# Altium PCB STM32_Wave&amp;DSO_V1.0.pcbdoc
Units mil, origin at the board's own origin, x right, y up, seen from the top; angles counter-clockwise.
Board outline 3421.85 x 1989.65 mil, 2 copper layers (Top Layer, Bottom Layer); 68 components, 46 nets, 295 pads, 187 vias.
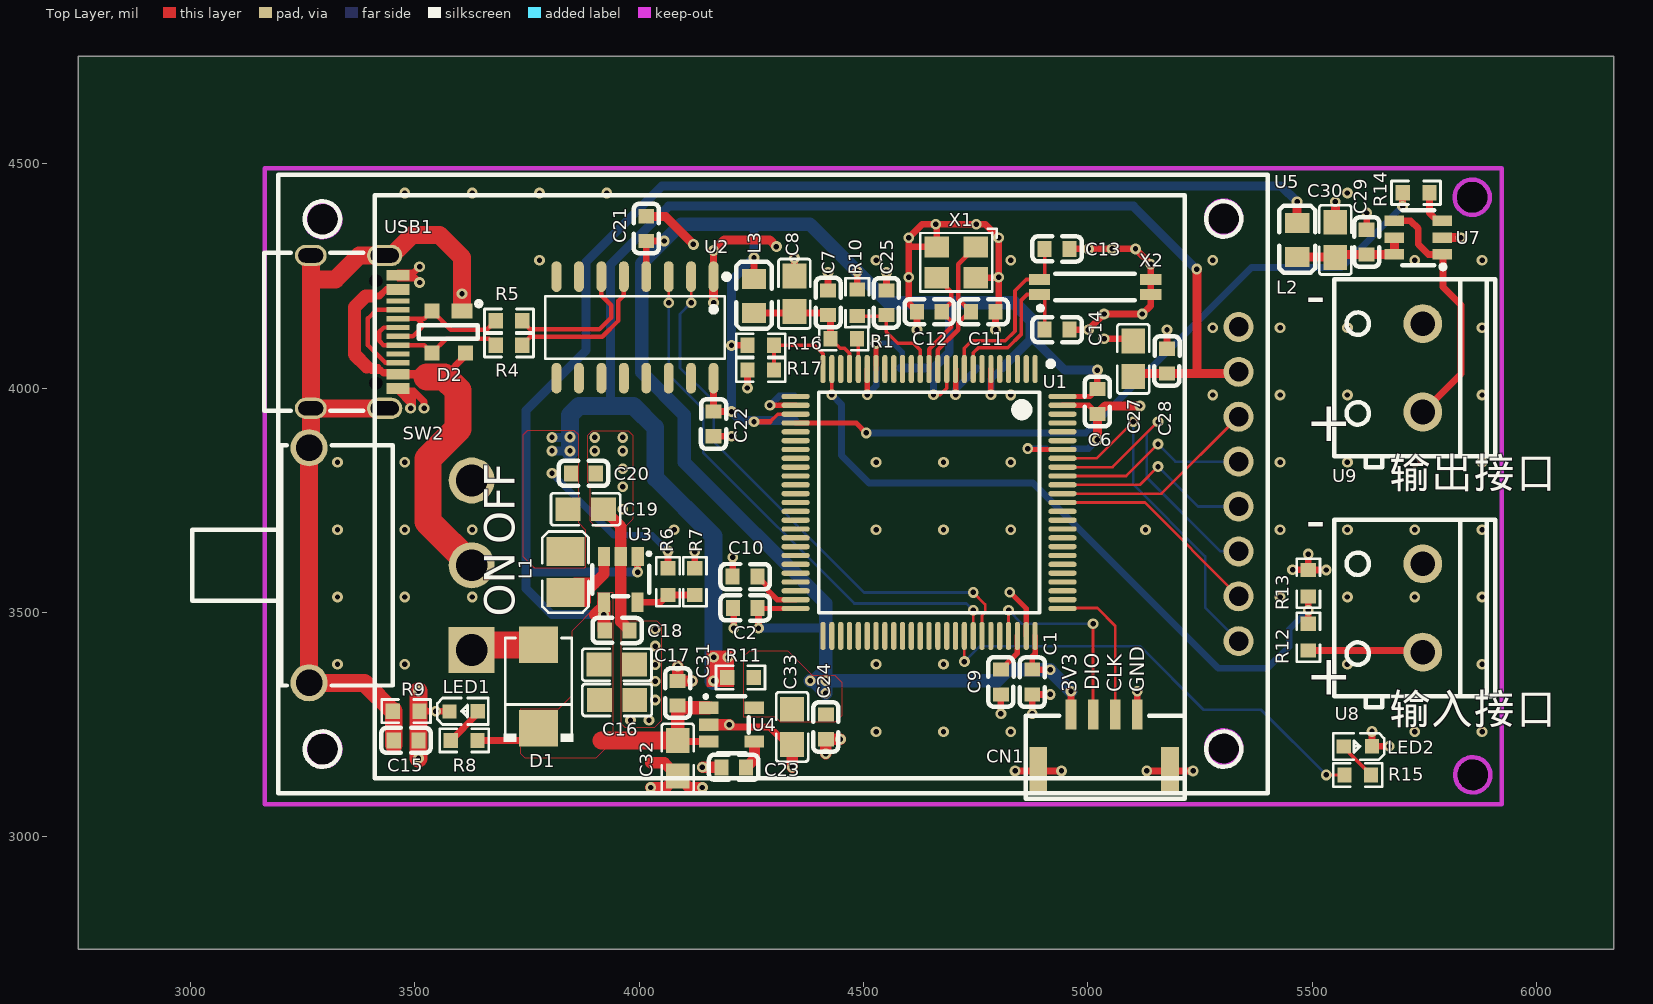
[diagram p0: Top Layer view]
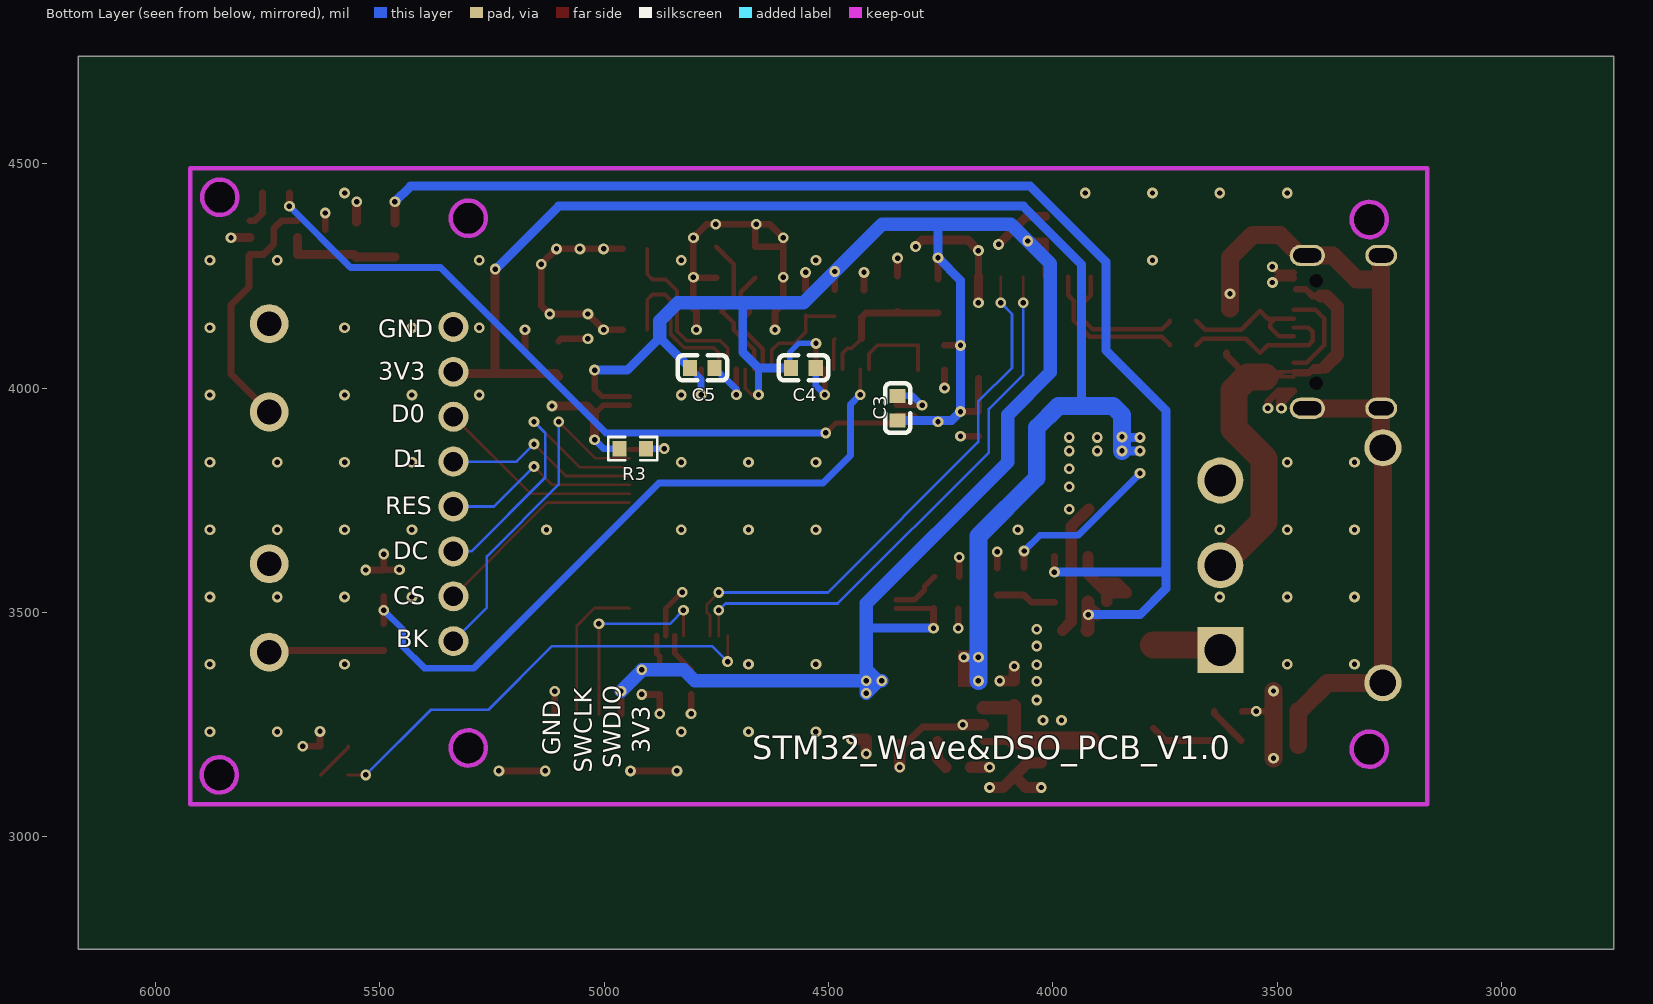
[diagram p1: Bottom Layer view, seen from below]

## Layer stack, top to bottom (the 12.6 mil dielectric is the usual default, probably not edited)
Top Layer: signal copper (thickness not stored)
Dielectric: dielectric 12.6, FR-4, Dk 4.8
Bottom Layer: signal copper (thickness not stored)

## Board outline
6171.85,2750 2750,2750 2750,4739.65 6171.85,4739.65
cut-out: 3334.43,4376.57 ccw(c3294.37,4376.57) 3254.31,4376.57 ccw(c3294.37,4376.57)
cut-out: 3334.41,3195.35 ccw(c3295.04,3195.35) 3255.67,3195.35 ccw(c3295.04,3195.35)
cut-out: 5341.57,3198.23 ccw(c5302.2,3198.23) 5262.83,3198.23 ccw(c5302.2,3198.23)
cut-out: 5896.57,3138.23 ccw(c5857.2,3138.23) 5817.83,3138.23 ccw(c5857.2,3138.23)
cut-out: 5895.31,4425 ccw(c5855.94,4425) 5816.57,4425 ccw(c5855.94,4425)
cut-out: 5342.25,4378.23 ccw(c5302.2,4378.23) 5262.16,4378.23 ccw(c5302.2,4378.23)

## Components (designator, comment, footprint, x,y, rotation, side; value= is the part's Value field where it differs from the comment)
C1 "0603B104K500NT" C0603 4875.94,3345 r90 top
C2 "0603B104K500NT" C0603 4236.55,3510 r0 top
C3 "0603B104K500NT" C0603 4345.94,3955 r270 bottom
C4 "0603B104K500NT" C0603 4555.94,4045 r0 bottom
C5 "0603B104K500NT" C0603 4781.06,4045 r0 bottom
C6 "0603B104K500NT" C0603 5020.94,3970 r90 top
C7 "0603B104K500NT" C0603 4420.94,4190 r270 top
C8 "GRM21BR61H106KE43L" C0805 4345.94,4210 r90 top
C9 "0603B104K500NT" C0603 4805.94,3345 r270 top
C10 "0603B104K500NT" C0603 4235.94,3580 r180 top
C11 "0603B104K500NT" C0603 4766.64,4170 r180 top
C12 "0603B104K500NT" C0603 4646.64,4170 r0 top
C13 "0603B104K500NT" C0603 4930.94,4310 r180 top
C14 "0603B104K500NT" C0603 4930.94,4130 r180 top
C15 "CAP_0603" C0603 3480.94,3215 r0 top
C16 "GRM21BR61H106KE43L" C0805 3950.94,3305 r180 top
C17 "GRM21BR61H106KE43L" C0805 3950.46,3383.67 r180 top
C18 "CC0603KRX7R9BB104" C0603 3950.94,3460 r180 top
C19 "GRM21BR61H106KE43L" C0805 3880.94,3730 r180 top
C20 "CC0603KRX7R9BB104" C0603 3875.94,3810 r180 top
C21 "CC0603KRX7R9BB104" C0603 4015.94,4355 r270 top
C22 "CC0603KRX7R9BB104" C0603 4165.94,3920 r90 top
C23 "CC0603KRX7R9BB104" C0603 4210.94,3155 r0 top
C24 "CC0603KRX7R9BB104" C0603 4415.94,3245 r90 top
C25 "0603B104K500NT" C0603 4550.94,4190 r90 top
C27 "GRM21BR61H106KE43L" C0805 5100.94,4065 r270 top
C28 "CC0603KRX7R9BB104" C0603 5175.94,4060 r270 top
C29 "CC0603KRX7R9BB104" C0603 5620.94,4325 r270 top
C30 "GRM21BR61H106KE43L" C0805 5550.94,4330 r270 top
C31 "CC0603KRX7R9BB104" C0603 4085.94,3320 r270 top
C32 "GRM21BR61H106KE43L" C0805 4085.94,3175 r90 top
C33 "GRM21BR61H106KE43L" C0805 4340.94,3245 r90 top
CN1 "X1251WRS-04HF-LPSW" CONN-SMD_4P-P1.25_X1251WRS-04HF-LPSW 5035.94,3210 r0 top
D1 "S2M_C232827" SMB_L4.6-W3.6-LS5.3-RD 3775.94,3335 r90 top
D2 "SESR05" SOT-143-4_L2.9-W1.3-P1.92-LS2.3-BL 3575.94,4125 r180 top
L1 "TFM252012ALMA4R7MTAA" L2520 3835.94,3590 r90 top
L2 "磁珠 0805 600Ω@100MHz CBW201209U601T" L0805 5465.94,4330 r270 top
L3 "磁珠 0805 600Ω@100MHz CBW201209U601T" L0805 4255.94,4205 r270 top
LED1 "LED_0603-R" LED_0603 3610.94,3280 r0 top
LED2 "LED_0603-R" LED_0603 5599.25,3201.55 r180 top
R1 "0603WAF0000T5E" R0603 4455.94,4110 r180 top
R3 "0603WAF0000T5E" R0603 4935.94,3865 r0 bottom
R4 "Res_0603" R0603 3710.26,4095 r180 top
R5 "Res_0603" R0603 3710.26,4150 r180 top
R6 "Res_0603" R0603 4064.2,3568.67 r270 top
R7 "Res_0603" R0603 4124.2,3568.67 r90 top
R8 "Res_0603" R0603 3610.26,3215 r0 top
R9 "Res_0603" R0603 3480.94,3280 r0 top
R10 "0603WAF0000T5E" R0603 4485.94,4190 r270 top
R11 "Res_0603" R0603 4225.94,3355 r180 top
R12 "Res_0603" R0603 5490.94,3445 r90 top
R13 "Res_0603" R0603 5490.94,3565 r90 top
R14 "Res_0603" R0603 5730.94,4435 r0 top
R15 "Res_0603" R0603 5601.13,3138.05 r180 top
R16 "0603WAF0000T5E" R0603 4270.94,4095 r0 top
R17 "0603WAF0000T5E" R0603 4270.94,4040 r180 top
SW2 "K3-1391B-51" SW-TH_K3-1391B-51 3445.94,3605 r270 top
U1 "STM32F407VET6" LQFP-100_L14.0-W14.0-P0.50-LS16.0-BL 4645.94,3745 r180 top
U2 "CH340C" SOP-16_L10.0-W3.9-P1.27-LS6.0-BL 3990.94,4135 r180 top
U3 "SY8089A1AAC" TSOT-23-5_L2.9-W1.6-P0.95-LS2.8-BR 3959.2,3573.67 r90 top
U4 "XC6228D122VR-G" TSOT-23-5_L2.9-W1.6-P0.95-LS2.8-BR 4205.94,3250 r180 top
U5 "TFT LCD 1.8" "TFT-LCD 1.8" 3185.94,4470 r270 top
U7 "OPA357AIDBVR" SOT-23-6_L2.9-W1.6-P0.95-LS2.8-BR 5735.94,4335 r0 top
U8 "KF300-5.0-2P" CONN-TH_P5.00_KF300-5.0-2P 5745.94,3510 r270 top
U9 "KF300-5.0-2P" CONN-TH_P5.00_KF300-5.0-2P 5745.94,4045 r270 top
USB1 "TYPE-C-31-M-12" USB-C_SMD-TYPE-C-31-M-12 3365.94,4125 r270 top
X1 "X32258MOB4SI" OSC-SMD_4P-L3.2-W2.5-BL 4706.64,4280 r180 top
X2 "M132768PWPAC" MC-146_4P-L6.7-W1.5-P0.85-BL 5015.94,4225 r0 top

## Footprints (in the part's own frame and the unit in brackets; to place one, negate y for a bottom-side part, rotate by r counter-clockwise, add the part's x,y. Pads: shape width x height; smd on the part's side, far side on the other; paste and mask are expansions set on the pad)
C0603 [mm]
  rect 0.8x0.9 smd paste+0 mask+0.051: 1(-0.7,0) 2(0.7,0)
  silkscreen extent -1.41,-0.71 1.39,0.72
C0805 [mm]
  rect 1.41x1.35 smd paste-100 mask+0.051: 1(-1,0) 2(1,0)
  silkscreen extent -1.96,-0.9 1.96,0.9
CONN-SMD_4P-P1.25_X1251WRS-04HF-LPSW [mm]
  rect 0.6x1.7 smd paste+0 mask+0.051: 1(-1.875,1.6) 2(-0.625,1.6) 3(0.625,1.6) 4(1.875,1.6)
  rect 1x2.7 smd paste+0 mask+0.051: 5(3.725,-1.6) 6(-3.725,-1.6)
  silkscreen extent -4.45,-3.18 4.57,1.52
CONN-TH_P5.00_KF300-5.0-2P [mm]
  round 2.2 hole 1.4 paste+0 mask+0.051: 1(2.5,0) 2(-2.5,0)
  silkscreen extent -5,-5 5.63,4.1
L0805 [mil]
  rect 44.59x54.21 smd paste-3937.01 mask+2: 1(-38.04,0) 2(38.04,0)
  silkscreen extent -77,-40 73,40
L2520 [mm]
  rect 1.635x2.16 smd paste-100 mask+0.051: 1(-1.168,0) 2(1.168,0)
  silkscreen extent -2.3,-1.31 2.3,1.31
LED_0603 [mil]
  rect 31.5x31.5 smd paste+0 mask+2: 1(-33.5,-0.4) 2(29.5,-0.2)
  silkscreen extent -61,-30 53,30
LQFP-100_L14.0-W14.0-P0.50-LS16.0-BL [mm]
  oval 0.3x1.6 smd paste-100 mask+0.051: 1(-6,-7.55) 2(-5.5,-7.55) 3(-5,-7.55) 4(-4.5,-7.55) 5(-4,-7.55) 6(-3.5,-7.55) 7(-3,-7.55) 8(-2.5,-7.55) 9(-2,-7.55) 10(-1.5,-7.55) 11(-1,-7.55) 12(-0.5,-7.55) 13(0,-7.55) 14(0.5,-7.55) 15(1,-7.55) 16(1.5,-7.55) 17(2,-7.55) 18(2.5,-7.55) 19(3,-7.55) 20(3.5,-7.55) 21(4,-7.55) 22(4.5,-7.55) 23(5,-7.55) 24(5.5,-7.55) 25(6,-7.55) 51(6,7.55) 52(5.5,7.55) 53(5,7.55) 54(4.5,7.55) 55(4,7.55) 56(3.5,7.55) 57(3,7.55) 58(2.5,7.55) 59(2,7.55) 60(1.5,7.55) 61(1,7.55) 62(0.5,7.55) 63(0,7.55) 64(-0.5,7.55) 65(-1,7.55) 66(-1.5,7.55) 67(-2,7.55) 68(-2.5,7.55) 69(-3,7.55) 70(-3.5,7.55) 71(-4,7.55) 72(-4.5,7.55) 73(-5,7.55) 74(-5.5,7.55) 75(-6,7.55)
  oval 1.6x0.3 smd paste-100 mask+0.051: 26(7.55,-6) 27(7.55,-5.5) 28(7.55,-5) 29(7.55,-4.5) 30(7.55,-4) 31(7.55,-3.5) 32(7.55,-3) 33(7.55,-2.5) 34(7.55,-2) 35(7.55,-1.5) 36(7.55,-1) 37(7.55,-0.5) 38(7.55,0) 39(7.55,0.5) 40(7.55,1) 41(7.55,1.5) 42(7.55,2) 43(7.55,2.5) 44(7.55,3) 45(7.55,3.5) 46(7.55,4) 47(7.55,4.5) 48(7.55,5) 49(7.55,5.5) 50(7.55,6) 76(-7.55,6) 77(-7.55,5.5) 78(-7.55,5) 79(-7.55,4.5) 80(-7.55,4) 81(-7.55,3.5) 82(-7.55,3) 83(-7.55,2.5) 84(-7.55,2) 85(-7.55,1.5) 86(-7.55,1) 87(-7.55,0.5) 88(-7.55,0) 89(-7.55,-0.5) 90(-7.55,-1) 91(-7.55,-1.5) 92(-7.55,-2) 93(-7.55,-2.5) 94(-7.55,-3) 95(-7.55,-3.5) 96(-7.55,-4) 97(-7.55,-4.5) 98(-7.55,-5) 99(-7.55,-5.5) 100(-7.55,-6)
  silkscreen extent -7.03,-8 6.25,6.25
MC-146_4P-L6.7-W1.5-P0.85-BL [mil]
  rect 47.24x23.62 smd paste+0 mask+2: 1(-124.02,-16.73) 2(124.02,-16.73) 3(124.02,16.73) 4(-124.02,16.73)
  silkscreen extent -127,-52 89,30
OSC-SMD_4P-L3.2-W2.5-BL [mm]
  rect 1.4x1.2 smd paste+0 mask+0.051: 1(-1.1,-0.875) 2(1.1,-0.875) 3(1.1,0.875) 4(-1.1,0.875)
  silkscreen extent -2.29,-1.9 2.03,1.65
R0603 [mil]
  rect 31.75x34.02 smd paste-3937.01 mask+2: 1(-29.66,0) 2(29.66,0)
  silkscreen extent -55,-26 55,26
SMB_L4.6-W3.6-LS5.3-RD [mil]
  rect 80.61x86.31 smd paste+0 mask+2: 1(-92.94,0) 2(92.94,0)
  silkscreen extent -123,-77 108,77
SOP-16_L10.0-W3.9-P1.27-LS6.0-BL [mm]
  oval 0.56x1.745 smd paste+0 mask+0.051: 1(-4.445,-2.872) 2(-3.175,-2.872) 3(-1.905,-2.872) 4(-0.635,-2.872) 5(0.635,-2.872) 6(1.905,-2.872) 7(3.175,-2.872) 8(4.445,-2.872) 9(4.445,2.872) 10(3.175,2.872) 11(1.905,2.872) 12(0.635,2.872) 13(-0.635,2.872) 14(-1.905,2.872) 15(-3.175,2.872) 16(-4.445,2.872)
  silkscreen extent -5.33,-3.02 5.08,1.77
SOT-23-6_L2.9-W1.6-P0.95-LS2.8-BR [mm]
  rect 1.1x0.6 smd paste+0 mask+0.051: 1(1.35,-0.95) 2(1.35,0) 3(1.35,0.95) 4(-1.35,0.95) 5(-1.35,0) 6(-1.35,-0.95)
  silkscreen extent -0.9,-1.78 1.52,1.55
SOT-143-4_L2.9-W1.3-P1.92-LS2.3-BL [mil]
  rect 47x33 smd paste+0 mask+2: 1(-29.53,-46.9)
  rect 33x33 smd paste+0 mask+2: 2(37.4,-46.9) 3(37.4,46.91) 4(-37.4,46.91)
  silkscreen extent -72,-69 67,15
SW-TH_K3-1391B-51 [mm]
  rect 2.6x2.6 hole 1.8 paste+0 mask+0.051: 1(4.8,4.6)
  round 2.6 hole 1.8 paste+0 mask+0.051: 2(0,4.6) 3(-4.8,4.6)
  round 2.1 hole 1.5 paste+0 mask+0.051: 4(-6.65,-4.6) 4(6.65,-4.6)
  silkscreen extent -6.8,-11.2 6.8,0.12
"TFT-LCD 1.8" [mm]
  round 1.7 hole 1.1 mask+0.051: 1(8.483,54.6) 2(11.023,54.6) 3(13.563,54.6) 4(16.103,54.6) 5(18.643,54.6) 6(21.183,54.6) 7(23.723,54.6) 8(26.263,54.6)
  silkscreen extent -0.13,0.25 34.87,56.25
TSOT-23-5_L2.9-W1.6-P0.95-LS2.8-BR [mm]
  rect 1.1x0.7 smd paste+0 mask+0.051: 1(1.294,-0.951) 2(1.294,-0.001) 3(1.294,0.951) 4(-1.294,0.951) 5(-1.294,-0.949)
  silkscreen extent -0.97,-1.65 1.52,1.61
USB-C_SMD-TYPE-C-31-M-12 [mm]
  oval 1.2x2 hole 0.8 slot 1.6 at 90 deg paste+0 mask+0.051: 1(4.325,1.706) 4(-4.325,1.706)
  oval 1.2x1.8 hole 0.8 slot 1.4 at 90 deg paste+0 mask+0.051: 2(4.325,-2.474) 3(-4.325,-2.474)
  rect 0.3x1.3 smd paste-100 mask+0.051: A1(-3.35,2.474) A4(-2.55,2.474) A5(-1.25,2.474) A6(-0.25,2.474) A7(0.25,2.474) A8(1.25,2.474) A9(2.55,2.474) A12(3.35,2.474) B1(3.05,2.474) B4(2.25,2.474) B5(1.75,2.474) B6(0.75,2.474) B7(-0.75,2.474) B8(-1.75,2.474) B9(-2.25,2.474) B12(-3.05,2.474)
  Multi-Layer board cut-out: -2.9,1.581 -3.063,1.544 -3.193,1.439 -3.266,1.289 -3.266,1.122 -3.193,0.972 -3.063,0.868 -2.9,0.831 -2.9,0.831 -2.737,0.868 -2.607,0.972 -2.534,1.122 -2.534,1.289 -2.607,1.439 -2.737,1.544 -2.9,1.581
  Multi-Layer board cut-out: 2.9,1.581 2.737,1.544 2.607,1.439 2.534,1.289 2.534,1.122 2.607,0.972 2.737,0.868 2.9,0.831 2.9,0.831 3.063,0.868 3.193,0.972 3.266,1.122 3.266,1.289 3.193,1.439 3.063,1.544 2.9,1.581
  silkscreen extent -4.47,-5.09 4.47,0.49

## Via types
v1: diameter 24, hole 12, Top Layer to Bottom Layer, 183 vias
v2: diameter 24.02, hole 12.01, Top Layer to Bottom Layer, 4 vias

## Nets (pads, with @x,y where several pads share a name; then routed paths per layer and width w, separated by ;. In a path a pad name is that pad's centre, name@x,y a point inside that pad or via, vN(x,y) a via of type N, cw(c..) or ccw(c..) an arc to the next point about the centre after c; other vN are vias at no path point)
3V3: C1.2 C2.2 C3.2 C4.2 C5.2 C6.2 C21.2 C22.2 C24.2 C33.2 CN1.1 L3.1 R10.1 R11.1 R16.1 U1.6 U1.11 U1.19 U1.28 U1.50 U1.75 U1.100 U2.4 U2.16 U4.5 | length 5415.7
  Top Layer w8: 4291.69,3925 4308.54,3941.85 U1.28 ; v1(4655.94,3985) 4670.94,3985 4685.31,3999.37 U1.11
  Top Layer w12: v1(4255.94,3925) 4291.69,3925 ; C2.2 4265.33,3508.78 U1.50 ; U1.19 v1(4527.83,4099.48) ; v1(4783.74,3985) U1.6 ; C1.2 4875.94,3402.04 4882.16,3408.26 U1.75 ; U1.100 5004.6,3981.22 C6.2
  Top Layer w15: U2.4 C21.2 v1(4055.94,4327.44) ; U2.16 C22.2 v1(4205.94,3947.56) ; v1(4205.94,4095) R16.1 ; L3.1 v1(4255.94,4290) ; C2.2@4265.33,3508.78 4265.94,3508.17 v1(4265.94,3465) ; R10.1 v1(4485.94,4259.66) ; C1.2 v1(4915.94,3372.56) ; CN1.1 v1(4962.12,3324.64) ; C6.2 v1(5020.94,4040)
  Bottom Layer w12: v1@4529.02,4099.48 4566.46,4099.48 4585.94,4080 4585.94,4047.44 C4.2
  Bottom Layer w15: v1(4255.94,3925) v1@4258.38,3927.44 ; v1(4527.83,4099.48) v1@4529.02,4099.48 ; v1(4655.94,3985) 4655.94,4045 ; v1(4783.74,3985) 4783.74,4020.12 C5.2
  Bottom Layer w20: 4252.46,4365 4255.94,4361.51 v1(4255.94,4290) 4205.94,4240 v1(4205.94,4095) v1(4205.94,3947.56) 4226.06,3927.44 4258.38,3927.44 C3.2 ; v1(4265.94,3465) 4415.1,3465 4415.94,3465.85 ; v1(4381.33,3347.78) 4409.1,3320 v1(4415.94,3320) ; v1@4383.57,3347.78 4415.94,3380.16 ; C4.2 4655.94,4045 4690.94,4080 4690.94,4186.7 4687.64,4190 ; C5.2 4875.94,4112.32 4948.26,4040 v1(5020.94,4040)
  Bottom Layer w30: v1(4381.33,3347.78) 4383.57,3347.78 v1(4415.94,3347.78) ; v1(4415.94,3320) v1(4415.94,3347.78) ; 4875.94,4112.32 4875.94,4150 4835.94,4190 4687.64,4190 4555.6,4190 v1(4485.94,4259.66) 4380.6,4365 4252.46,4365 4093.5,4365 v1(4055.94,4327.44) 4005.94,4277.44 4005.94,4035 4100.94,3940 4100.94,3835 4415.94,3520 4415.94,3465.85 4415.94,3380.16 v1(4415.94,3347.78) ; v1(4962.12,3324.64) 4915.94,3370.82 v1(4915.94,3372.56) 4822.37,3372.56 4797.58,3347.78 v1(4415.94,3347.78)
$1N1024: R1.1 U1.21 | length 68.9
  Top Layer w8: R1.1 4488.46,4107.14 U1.21
$1N1612: C9.1 U1.73 | length 90.5
  Top Layer w12: C9.1 4842.79,3409.41 U1.73
$1N1616: C10.1 U1.49 | length 111
  Top Layer w12: C10.1 4285.94,3557.56 4285.94,3550 4307.48,3528.46 U1.49
$1N1686: R3.1 U1.94 | length 118.4
  Top Layer w12: v1(4865.94,3865) 4867.83,3863.11 U1.94
  Bottom Layer w15: v1(4865.94,3865) R3.1
$1N2945: LED2.2 R15.1 | length 89
  Top Layer w8: LED2.2 5569.75,3199.09 R15.1
$2N936: LED1.2 R8.1 | length 89.6
  Top Layer w15: R8.1 3640.44,3274.84 LED1.2
$2N944: USB1.A5 USB1.B5 | length 218.9
  Top Layer w10: USB1.B5 3434.84,4056.1 3395.94,4095 3395.94,4155 3415.15,4174.21 USB1.A5
$2N953: L1.1 U3.3 | length 234.6
  Top Layer w25: 3879.98,3525 3879.98,3544.03 ; U3.3 3921.77,3585.82 3900.94,3565 ; 3879.98,3544.03 3900.94,3565 ; 3879.98,3544.03 L1.1 3856.91,3565 3900.94,3565
$2N955: R6.2 R7.1 U3.5 | length 134.4
  Top Layer w15: U3.5 4047.92,3522.72 R6.2 R7.1
$2N958: D1.2 SW2.1 | length 153.8
  Top Layer w60: SW2.1 3638.96,3427.94 D1.2
$2N959: D2.4 SW2.2 USB1.A4 USB1.A9 USB1.B4 USB1.B9 | length 1196.5
  Top Layer w8: 3425.51,4037.87 USB1.B4@3461.9,4037.87 ; USB1.A9 3463.75,4025 3527.42,4025 3522.42,4030 ; USB1.B4@3463.35,4037.87 USB1.B4@3461.9,4037.87 ; USB1.B4@3461.9,4037.87 USB1.B4 USB1.B4@3484.52,4036.42 ; USB1.B4@3484.52,4036.42 3490.94,4030 3522.42,4030 ; USB1.B4@3484.52,4036.42 3516,4036.42 3522.42,4030
  Top Layer w12: USB1.B4 3458.35,4031.42 3430.51,4031.42 3424.06,4037.87 ; 3424.06,4037.87 3426.18,4040 3418.86,4047.32 3393.27,4047.32 3402.99,4037.59 3423.77,4037.59 3424.06,4037.87
  Top Layer w15: 3402.85,4205 3421.75,4205 3436.75,4220 USB1.A4@3457.96,4220 ; 3565.94,4025 3613.34,4072.4 D2.4
  Top Layer w30: 3393.27,4047.32 3365.94,4074.64 3365.94,4180 3390.94,4205 3402.85,4205
  Top Layer w60: 3527.42,4025 3565.94,4025 3596.78,3994.16 3596.78,3909.31 3529.26,3841.79 3529.26,3702.79 SW2.2
$2N961: D2.3 R4.2 USB1.A6 USB1.B6 | length 356.7
  Top Layer w10: USB1.A6 3430.76,4134.84 3420.94,4125.02 3420.94,4105 3430.47,4095.47 USB1.B6 3521.17,4095.47 D2.3 3570.45,4110 3665.6,4110 R4.2
$2N962: D2.2 R5.2 USB1.A7 USB1.B7 | length 334.7
  Top Layer w10: USB1.A7 3496.1,4115.16 3515.94,4135 3515.94,4144.33 3505.74,4154.53 ; USB1.B7 3505.74,4154.53 ; R5.2 3660.6,4130 3580.45,4130 D2.2 3521.17,4154.53 3505.74,4154.53
$2N1330: C23.2 U4.4 | length 65.2
  Top Layer w25: C23.2 4256.89,3173.39 U4.4
$3N734: R12.1 U8.1 | length 256.6
  Top Layer w15: R12.1 5742.19,3415.34 U8.1
$3N1011: R14.2 U7.3 | length 80.6
  Top Layer w15: R14.2 5760.94,4434.66 5760.94,4390 5778.54,4372.4 U7.3
$3N1098: U7.1 U7.4 U9.1 | length 561.3
  Top Layer w15: U7.4 5718.54,4372.4 5735.94,4355 5735.94,4320 5758.34,4297.6 U7.1 5790.94,4295.75 5790.94,4225 5830.94,4185 5830.94,4031.58 U9.1
+4V9: C16.2 C17.2 C18.2 C31.2 C32.2 D1.1 L2.1 R8.2 U3.1 U3.4 U4.1 U4.3 | length 3611.5
  Top Layer w15: R8.2 3748.88,3215 D1.1 ; v1(3996.65,3590) U3.1 ; C32.2 4087.75,3212.56 U4.3
  Top Layer w20: L2.1 v1(5465.94,4415)
  Top Layer w25: 3900.94,3495 U3.4@3921.77,3515.82
  Top Layer w30: U3.4 3921.77,3515.82 3921.77,3461.62 C18.2 ; C32.2 C31.2 4090.94,3287.44 U4.1
  Top Layer w40: 3915.94,3214.37 C32.2
  Bottom Layer w20: v1(3920.94,3495) 3805.94,3495 3748.12,3552.82 3748.12,3598.22 ; v1(3996.65,3590) 3756.34,3590 3748.12,3598.22 ; v1(5465.94,4415) 5430.94,4450 4050.94,4450 3881.9,4280.95 3881.9,4084.27 3748.12,3950.49 3748.12,3598.22
ADC123_IN1: R12.2 R13.1 U1.24 | length 1574.3
  Top Layer w8: v1(4429.4,3985) U1.24
  Top Layer w15: R12.2 v1(5490.94,3505) R13.1
  Bottom Layer w15: v1(4429.4,3985) 4450.94,3963.46 4450.94,3850 4512.28,3788.66 4877.28,3788.66 5290.11,3375.84 5400.3,3375.84 5448.44,3423.98 5448.44,3462.5 v1(5490.94,3505)
DAC_OUT1: R14.1 U1.29 | length 1600.7
  Top Layer w12: U1.29 4483.77,3922.17 v1(4505.94,3900)
  Top Layer w15: v1(5700.94,4405) 5700.94,4434.66 R14.1
  Bottom Layer w15: v1(4505.94,3900) 4995.94,3900 5364.37,4268.43 5564.37,4268.43 v1(5700.94,4405)
EXT_GND: C15.1 D2.1 R9.1 SW2.4 USB1.1 USB1.2 USB1.3 USB1.4 | length 1921.2
  Top Layer w40: USB1.3 3268.54,4242.2 ; USB1.1 USB1.2 ; C15.1@3453.38,3205 C15.1 R9.1@3453.38,3277.9 ; R9.1@3453.38,3280 R9.1@3453.38,3277.9 ; D2.1@3605.47,4176.9 v1(3605.47,4210) 3605.47,4290.75 3555.32,4340.9 3494.47,4340.9 3448.85,4295.28 USB1.4 3376.53,4295.28 3323.45,4242.2 3268.54,4242.2 ; USB1.2 3268.54,4242.2 ; USB1.2 3268.54,3870.51 3264.84,3866.82 3264.84,3343.18 3388.1,3343.18 R9.1 R9.1@3453.38,3277.9
GND: C1.1 C2.1 C3.1 C4.1 C5.1 C6.1 C7.1 C8.2 C9.2 C10.2 C11.1 C12.1 C13.1 C14.1 C15.2 C16.1 C17.1 C18.1 C19.1 C20.1 C21.1 C22.1 C23.1 C24.1 C25.2 C27.1 C28.1 C29.1 C30.1 C31.1 C32.1 C33.1 CN1.4 CN1.5 CN1.6 LED1.1 LED2.1 R3.2 R7.2 R9.2 R13.2 R17.2 U1.10 U1.20 U1.27 U1.74 U1.99 U2.1 U3.2 U4.2 U5.1 U7.2 U8.2 U9.2 USB1.A1 USB1.A12 USB1.B1 USB1.B12 X1.2 X1.4 X2.2 X2.3 | length 5066.6
  Top Layer w12: v1(4291.46,3961.54) U1.27 ; v1(4508.14,3985) U1.20 ; v1(4705,3985) U1.10 ; v1(4825.94,3545) 4862.48,3508.46 U1.74 ; U1.99 5001.84,3961.54 C6.1
  Top Layer w15: USB1.B12 3500.86,4245.08 v1(3510.94,4235) ; USB1.A1 3497.75,4256.89 v1(3510.94,4270.08) ; R9.2 v1(3546.96,3280) 3577.04,3280 LED1.1 ; v1(3520.94,3955) 3520.94,3970 3497.83,3993.11 USB1.A12@3477.83,3993.11 ; R7.2 v1(4124.2,3635) ; C22.1 v1(4205.94,3892.44) ; U2.1 v1(4165.94,4306.18) ; v1(4200.94,3250.04) 4205.99,3245 4290.94,3245 4330.31,3205.63 C33.1 ; C10.2 v1(4208.38,3623.05) ; v1(4210.94,3465) C2.1@4210.94,3508.05 ; v1(4241.28,4000) R17.2 ; C8.2 v1(4345.94,4289.37) ; C7.1 v1(4420.94,4257.56) ; C25.2 v1(4550.94,4257.56) ; v1(4619.08,4130) C12.1 4600.94,4188.14 v1(4600.94,4246.97) 4600.94,4313.26 ; X1.4 4799.52,4245.55 v1(4800.94,4246.97) ; v1(4794.2,4130) C11.1 4800.94,4176.74 v1(4800.94,4246.97) ; v1(4805.94,3274.39) C9.2 ; v1(4837.64,3147.01) CN1.6 v1(4940.94,3147.01) ; v1(4875.94,3274.39) C1.1 v1(4915.94,3317.44) ; C14.1 v1(5000.94,4130) v1(5035.94,4165) v1(5120.94,4165) 5139.96,4184.02 X2.2 X2.3 v1(5139.96,4275.98) v1(5105.94,4310) v1(5053.78,4310) v1(5000.94,4310) C13.1 ; v1(5035.94,4110) 5095.31,4110 C27.1 ; CN1.4 v1(5109.76,3324.64) ; v1(5130.94,3147.01) CN1.5 v1(5234.24,3147.01) ; C28.1 v1(5175.94,4130) ; v1(5455.94,3595) 5490.6,3595 R13.2 ; v1(5490.94,3630) R13.2 ; v1(5530.94,3594.66) R13.2 ; C29.1 v1(5620.94,4390) ; v1(5632.75,3235) LED2.1 v1(5670.94,3201.95) ; USB1.A12@3477.83,3993.11 3495.94,3975 3495.94,3960 v1(3490.94,3955) 3490.94,3965.52 USB1.A12 USB1.A12@3477.83,3993.11 ; 4600.94,4313.26 4602.13,4314.45 X1.2 4663.33,4362.61 v1(4660.94,4365) ; 4600.94,4313.26 v1(4600.94,4335) 4630.94,4365 v1(4660.94,4365) ; v1(4660.94,4365) v1(4750.94,4365) 4770.94,4365 v1(4800.94,4335) v1(4800.94,4246.97)
  Top Layer w20: C21.1 4058.38,4382.56 v1(4120.94,4320) ; v1(4165.94,4190) U2.1 ; v1(4165.94,4306.18) 4189.76,4330 4290.94,4330 v1(4305.94,4315) ; v1(5020.94,3885) C6.1 5038.5,3960 v1(5115.94,3960) ; C30.1 v1(5550.94,4415) ; U7.2 v1(5830.94,4335)
  Top Layer w25: C19.1 3959.25,3691.07 U3.2 3959.25,3479.26 C18.1 ; v1(4025.94,3110) 4060.31,3110 C32.1 ; 4025.94,3165 4056.57,3165 C32.1 ; v1(4085.94,3380) C31.1 v1(4118.38,3347.56) ; v1(4140.94,3110) 4111.57,3110 C32.1 ; v1(4140.94,3155) C23.1 ; U4.2 v1(4200.94,3250.04) ; v1(4340.94,3155) C33.1 ; v1(4415.94,3185) C24.1 v1(4448.38,3217.44)
  Top Layer w40: v1(3508.5,3175) C15.2 3508.5,3277.9 R9.2 3508.5,3282.1 v1(3508.5,3325)
  Bottom Layer w15: v1(4291.46,3961.54) 4312.48,3982.56 C3.1 ; v1(4508.14,3985) 4528.38,4005.24 C4.1 ; v1(4705,3985) 4705,3996.5 C5.1 ; R3.2 5000.94,3865 v1(5020.94,3885)
  other v1: 4528.04,3234.42 4678.04,3234.42 4828.04,3234.42 5728.04,3234.42 5878.04,3234.42 3980.94,3260 4022.05,3260 4035.94,3305 4035.94,3346.84 3328.04,3384.42 3478.04,3384.42 4035.94,3383.67 4528.04,3384.42 4678.04,3384.42 5578.04,3384.42 5878.04,3384.42 4035.94,3425 4035.94,3462.43 3328.04,3534.42 3478.04,3534.42 3628.04,3534.42 5428.04,3534.42 5578.04,3534.42 5728.04,3534.42 5878.04,3534.42 3328.04,3684.42 3478.04,3684.42 3628.04,3684.42 4078.04,3684.42 4528.04,3684.42 4678.04,3684.42 4828.04,3684.42 5128.04,3684.42 5428.04,3684.42 5578.04,3684.42 5728.04,3684.42 5878.04,3684.42 3963.35,3730 3963.35,3780 3963.35,3820 3328.04,3834.42 3478.04,3834.42 4528.04,3834.42 4678.04,3834.42 4828.04,3834.42 5428.04,3834.42 5578.04,3834.42 5728.04,3834.42 5878.04,3834.42 3900.94,3860 3963.35,3860 3900.94,3890 3963.35,3890 4828.04,3984.42 5278.04,3984.42 5428.04,3984.42 5578.04,3984.42 5878.04,3984.42 5278.04,4134.42 5428.04,4134.42 5578.04,4134.42 5878.04,4134.42 3778.04,4284.42 4528.04,4284.42 4828.04,4284.42 5278.04,4284.42 5728.04,4284.42 5878.04,4284.42 3478.04,4434.42 3628.04,4434.42 3778.04,4434.42 3928.04,4434.42 5578.04,4434.42
LCD_BK: U1.93 U5.8 | length 777.7
  Top Layer w6: U1.93 5019.37,3843.43 v2(5100.94,3925)
  Bottom Layer w6: v2(5100.94,3925) 5100.94,3785.15 5260.94,3625.15 5260.94,3510.63 U5.8
LCD_CLK: U1.89 U5.3 | length 463.3
  Top Layer w6: U1.89 5164.2,3764.68 U5.3
LCD_CS: U1.88 U5.7 | length 478.9
  Top Layer w6: U1.88 5126.57,3745 U5.7
LCD_DATA: U1.91 U5.4 | length 437.9
  Top Layer w6: U1.91 5085,3804.06 v2(5155.94,3875)
  Bottom Layer w6: v2(5155.94,3875) 5194.92,3836.02 U5.4
LCD_DC: U1.92 U5.6 | length 662.5
  Top Layer w6: U1.92 5054.68,3823.74 v2(5155.94,3925)
  Bottom Layer w6: v2(5155.94,3925) 5130.94,3900 5130.94,3800.16 5295.08,3636.02 U5.6
LCD_RES: U1.90 U5.5 | length 446
  Top Layer w6: U1.90 5115.31,3784.37 v2(5155.94,3825)
  Bottom Layer w6: v2(5155.94,3825) 5244.92,3736.02 U5.5
LED0: R15.2 U1.67 | length 1037.2
  Top Layer w6: v1(4724.68,3390.52) U1.67 ; v1(5530.94,3138.05) R15.2
  Bottom Layer w6: v1(4724.68,3390.52) 4759.16,3425 5115.94,3425 5257.67,3283.27 5385.72,3283.27 v1(5530.94,3138.05)
OSC32_IN: C14.2 U1.8 X2.1 | length 364.9
  Top Layer w8: U1.8 4744.37,4078.43 4755.94,4090 4821.61,4090 4850.94,4119.33 4850.94,4195 4864.21,4208.27 X2.1 4903.38,4196.81 C14.2
OSC32_OUT: C13.2 U1.9 X2.4 | length 403.1
  Top Layer w8: U1.9 4724.68,4088.74 4740.94,4105 4815.94,4105 4837.44,4126.5 4837.44,4216.88 4862.3,4241.73 X2.4 4903.38,4253.19 C13.2
OSC_IN: C11.2 U1.12 X1.1 | length 332.3
  Top Layer w10: U1.12 4665.62,4084.68 4710.94,4130 4710.94,4145 4735.94,4170 C11.2 4710.94,4198.14 4710.94,4275.44 X1.1
OSC_OUT: C12.2 U1.13 X1.3 | length 255.3
  Top Layer w10: U1.13 4645.94,4086.21 4695.94,4136.21 4695.94,4148.26 C12.2 4695.62,4191.42 4695.62,4213.26 X1.3
RESET: C25.1 R10.2 U1.14 | length 237.8
  Top Layer w8: R10.2 4548.84,4160.34 C25.1 4550.94,4125 4575.94,4100 4610.94,4100 4626.25,4084.69 U1.14
SWCLK: CN1.3 U1.76 | length 331.7
  Top Layer w6: U1.76 4944.4,3510 5020.94,3510 5060.55,3470.39 CN1.3
SWDIO: CN1.2 U1.72 | length 460.2
  Top Layer w6: U1.72 v1(4823.11,3505) ; v1@5010.94,3475 v1(5011.33,3474.61) CN1.2
  Bottom Layer w6: v1(4823.11,3505) 4853.5,3474.61 v1(5011.33,3474.61)
USART1_RX: U1.69 U2.2 | length 1237.8
  Top Layer w6: v1(4115.94,4190) U2.2 ; v1(4744.37,3544.66) 4770.94,3518.09 4770.94,3500 4764.05,3493.11 U1.69
  Bottom Layer w6: v1(4115.94,4190) 4090.94,4165 4090.94,4045 4166.38,3969.57 4166.38,3879.31 4501.03,3544.66 v1(4744.37,3544.66)
USART1_TX: U1.68 U2.3 | length 1227.8
  Top Layer w6: v1(4065.94,4190) U2.3 ; U1.68 v1(4744.37,3505)
  Bottom Layer w6: v1(4065.94,4190) 4065.94,4030 4142.6,3953.34 4142.6,3856.83 4479.43,3520 4729.37,3520 v1(4744.37,3505)
USB_DM: R5.1 U2.6 | length 318.5
  Top Layer w10: R5.1 3739.92,4147.88 3757.3,4130.5 3911.44,4130.5 3937.94,4157 3937.94,4184.74 3915.94,4206.74 U2.6
USB_DP: R4.1 U2.5 | length 340.9
  Top Layer w10: R4.1 3739.92,4097.12 3757.3,4114.5 3918.07,4114.5 3953.94,4150.37 3953.94,4194.74 3965.94,4206.74 U2.5
VCC: C29.2 C30.2 L2.2 U7.5 U7.6 | length 257.7
  Top Layer w20: L2.2 5549.61,4291.96 C30.2 5557.91,4297.6 U7.6 U7.5
VDDA: C7.2 C8.1 L3.2 R1.2 U1.22 | length 317.7
  Top Layer w8: R1.2 4447.96,4088.32 4457.62,4088.32 4468.77,4077.17 U1.22
  Top Layer w15: L3.2 C8.1@4342.27,4166.96 ; C8.1 C8.1@4342.27,4166.96 ; R1.2 4426.28,4157.1 C7.2 4416.42,4166.96 C8.1@4342.27,4166.96
VER: R16.2 R17.1 U1.25 | length 205.9
  Top Layer w8: R17.1 R16.2 4390.94,4095 4409.72,4076.22 U1.25
VIN_3V3: C19.2 C20.2 C27.2 C28.2 L1.2 R6.1 R11.2 U5.2 | length 3601.2
  Top Layer w15: R6.1@4064.2,3600.16 v1(4064.2,3636.84)
  Top Layer w20: C27.2 5107.75,4032.44 C28.2 5242.92,4032.44 ; v1(5242.38,4265) 5242.38,4032.98 5242.92,4032.44 ; U5.2 5331.96,4032.44 5242.92,4032.44
  Bottom Layer w15: v1(3805.94,3810) 3944.11,3671.84 4029.2,3671.84 v1(4064.2,3636.84)
  Bottom Layer w20: v1(3805.94,3860) v1(3845.94,3860) ; v1(3805.94,3890) 3844.92,3890 v1(3845.94,3891.02) ; 3930.94,3960 3935.94,3965 3935.94,4275 4065.94,4405 5100.94,4405 v1@5240.94,4265 ; v1(4165.94,3400) v1(4198.28,3400)
  Bottom Layer w40: v1(3845.94,3860) v1(3845.94,3891.02) 3845.94,3940 3865.94,3960 3930.94,3960 3987.51,3960 4035.94,3911.57 4035.94,3800 4165.94,3670 v1(4165.94,3400) v1@4165.94,3347.58
  other v1: 4165.97,3347.56
"": SW2.3 U1.1 U1.2 U1.3 U1.4 U1.5 U1.7 U1.15 U1.16 U1.17 U1.18 U1.23 U1.26 U1.30 U1.31 U1.32 U1.33 U1.34 U1.35 U1.36 U1.37 U1.38 U1.39 U1.40 U1.41 U1.42 U1.43 U1.44 U1.45 U1.46 U1.47 U1.48 U1.51 U1.52 U1.53 U1.54 U1.55 U1.56 U1.57 U1.58 U1.59 U1.60 U1.61 U1.62 U1.63 U1.64 U1.65 U1.66 U1.70 U1.71 U1.77 U1.78 U1.79 U1.80 U1.81 U1.82 U1.83 U1.84 U1.85 U1.86 U1.87 U1.95 U1.96 U1.97 U1.98 U2.7 U2.8 U2.9 U2.10 U2.11 U2.12 U2.13 U2.14 U2.15 USB1.A8 USB1.B8

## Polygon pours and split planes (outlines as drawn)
GND on Top Layer (solid, remove dead copper, pour order 6): 3165.94,3072.28 5921.84,3072.28 5921.84,4489.58 3165.94,4489.58
+4V9 on Top Layer (solid, remove dead copper, pour order 0): 3735.94,3285 3820.94,3285 3850.94,3315 3850.94,3459.28 3908.42,3516.76 3908.42,3545 3940.94,3545 3940.94,3212.73 3903.21,3175 3745.94,3175 3735.94,3185
VIN_3V3 on Top Layer (solid, remove dead copper, pour order 1): 3880.94,3601.84 3880.94,3683.61 3865.15,3699.41 3865.15,3895.8 3855.94,3905 3750.94,3905 3740.94,3895 3740.94,3625 3765.94,3600 3879.11,3600
GND on Top Layer (solid, remove dead copper, pour order 2): 3890.94,3785 3885.94,3790 3885.94,3895 3895.94,3905 3975.94,3905 3985.94,3895 3985.94,3707.76 3969.25,3691.07 3903.45,3691.07 3890.94,3703.57
3V3 on Top Layer (solid, remove dead copper, pour order 3): 4233.1,3267.05 4233.1,3402.16 4245.94,3415 4330.94,3415 4385.94,3360 4435.94,3360 4450.94,3345 4450.94,3270 4435.94,3255 4315.94,3255 4303.9,3267.05
GND on Bottom Layer (solid, remove dead copper, pour order 4): 3165.94,3072.28 5921.84,3072.28 5921.84,4489.58 3165.94,4489.58
GND on Top Layer (solid, remove dead copper, pour order 5): 4035.37,3244.43 4050.94,3260 4050.1,3461.36 4050.94,3470 4040.94,3480 3964.13,3480 3959.65,3475.53 3959.65,3252.89 3968.12,3244.43

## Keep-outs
Board Outline Layer:
  circle w10 net "": c5855.94,4425 r39.37
  circle w10 net "": c5857.2,3138.23 r39.37
  circle w10 net "": c3295.04,3195.35 r39.37
  circle w10 net "": c3295.04,4375.35 r39.37
  circle w10 net "": c5302.2,3198.23 r39.37
  circle w10 net "": c5302.2,4378.23 r39.37
  lines w10 net "": 3165.94,3072.32 5921.85,3072.32 5921.85,4489.65 3165.94,4489.65 3165.94,3072.32

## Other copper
Top Layer:
  region net VIN_3V3: 4150.94,3335 4210.94,3335 4210.94,3415 4150.94,3415

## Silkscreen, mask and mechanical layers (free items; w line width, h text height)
Top Silkscreen Layer:
  text "-" at 5485.6,4161.72 h90.62
  text "+" at 5485.6,3881.67 h90.62
  text "输出接口" at 5671.19,3777.54 h67.97
  text "-" at 5485.6,3661.72 h90.62
  text "OFF" at 3723.4,3652.45 h67.97 r90
  text "ON" at 3723.4,3489.91 h67.97 r90
  text "DIO" at 5024.84,3327.23 h32.45 r90
  text "3V3" at 4974.84,3322.23 h32.45 r90
  text "CLK" at 5074.84,3322.23 h32.45 r90
  text "GND" at 5124.84,3322.23 h32.45 r90
  text "+" at 5485.6,3316.72 h90.62
  text "输入接口" at 5671.19,3252.54 h67.97
Bottom Silkscreen Layer:
  text "GND" at 5502.62,4113.32 h38.94
  text "3V3" at 5502.62,4018.32 h38.94
  text "D0" at 5474.33,3923.32 h38.94
  text "D1" at 5469.33,3823.32 h38.94
  text "RES" at 5487.62,3718.32 h38.94
  text "DC" at 5469.33,3618.32 h38.94
  text "CS" at 5469.33,3518.32 h38.94
  text "BK" at 5463.32,3422.66 h38.94
  text "3V3" at 4897.62,3186.68 h38.94 r270
  text "GND" at 5097.62,3181.68 h38.94 r270
  text "STM32_Wave&DSO_PCB_V1.0" at 4669.52,3172.76 h51.92
  text "SWDIO" at 4962.62,3153.26 h38.94 r270
  text "SWCLK" at 5027.62,3143.26 h38.94 r270
Mechanical Layer:
  circle w1 net "": c3294.37,4376.57 r40.06
  circle w1 net "": c3295.04,3195.35 r39.37
  circle w1 net "": c5302.2,3198.23 r39.37
  circle w1 net "": c5857.2,3138.23 r39.37
  circle w1 net "": c5855.94,4425 r39.37
  circle w1 net "": c5302.2,4378.23 r40.04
